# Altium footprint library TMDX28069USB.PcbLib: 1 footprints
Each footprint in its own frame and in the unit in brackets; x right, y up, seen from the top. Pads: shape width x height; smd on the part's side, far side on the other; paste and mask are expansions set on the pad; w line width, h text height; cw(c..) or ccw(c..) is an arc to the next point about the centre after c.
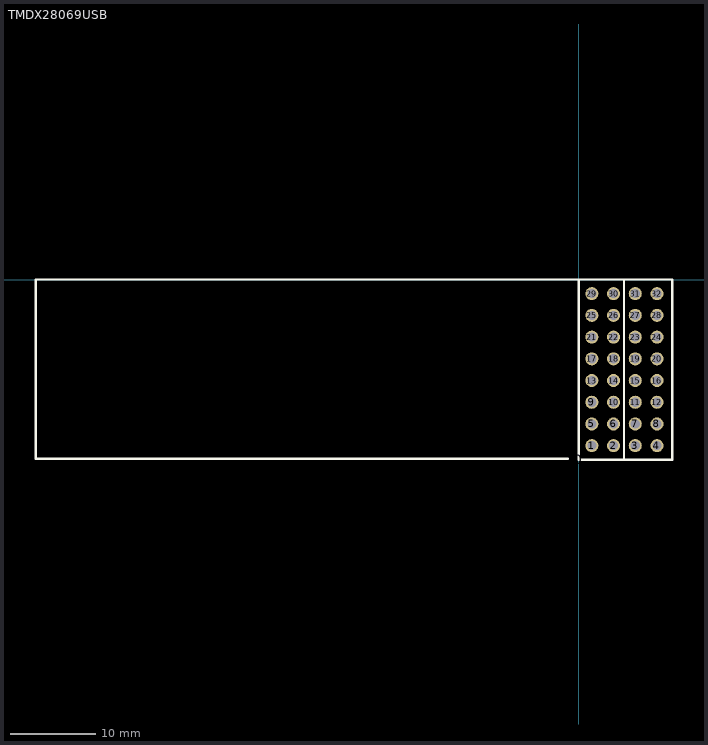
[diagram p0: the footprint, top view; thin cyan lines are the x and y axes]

## TMDX28069USB [mil] "USE TWO SAMTEC SSW-108-01-T-D IN PARALLEL"
height 350
pads (33):
  round 80 on Top Overlay: 0(0,-830)
  round 60 hole 42: 1(60,-765) 2(160,-765) 3(260,-765) 4(360,-765) 5(60,-665) 6(160,-665) 7(260,-665) 8(360,-665) 9(60,-565) 10(160,-565) 11(260,-565) 12(360,-565) 13(60,-465) 14(160,-465) 15(260,-465) 16(360,-465) 17(60,-365) 18(160,-365) 19(260,-365) 20(360,-365) 21(60,-265) 22(160,-265) 23(260,-265) 24(360,-265) 25(60,-165) 26(160,-165) 27(260,-165) 28(360,-165) 29(60,-65) 30(160,-65) 31(260,-65) 32(360,-65)
Top Overlay:
  lines w10: -50,-825 -2500,-825 -2500,0 0,0 ; 208.66,-830 208.66,0 ; 0,0 430,0 430,-830 0,-830 0,0
3D body: height 350, standoff 0, extent 0,-830.71 430,0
